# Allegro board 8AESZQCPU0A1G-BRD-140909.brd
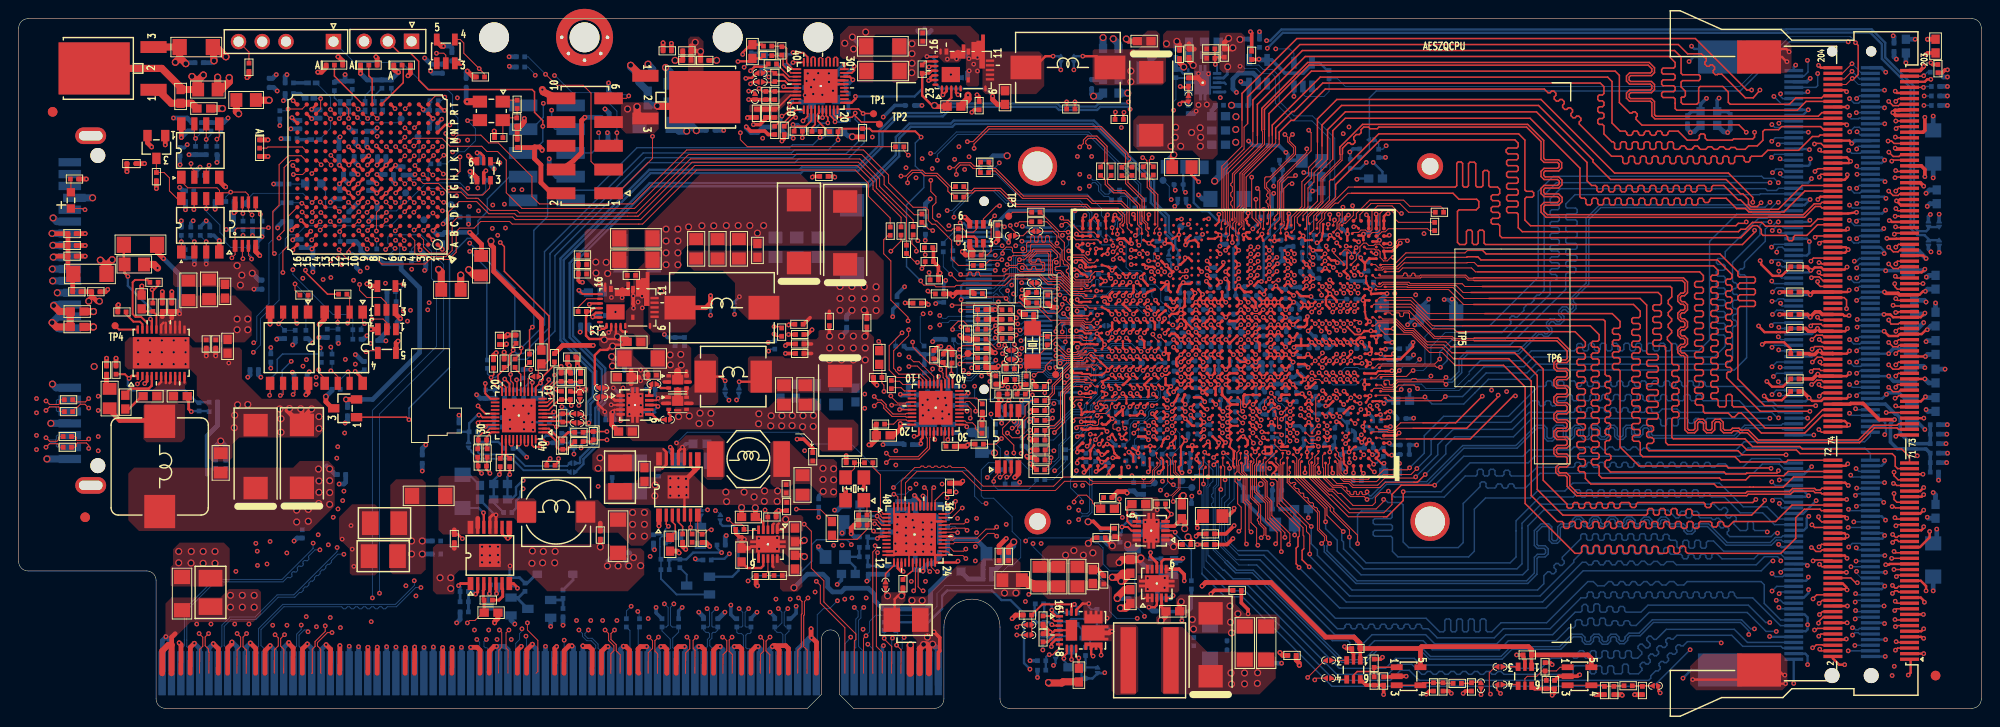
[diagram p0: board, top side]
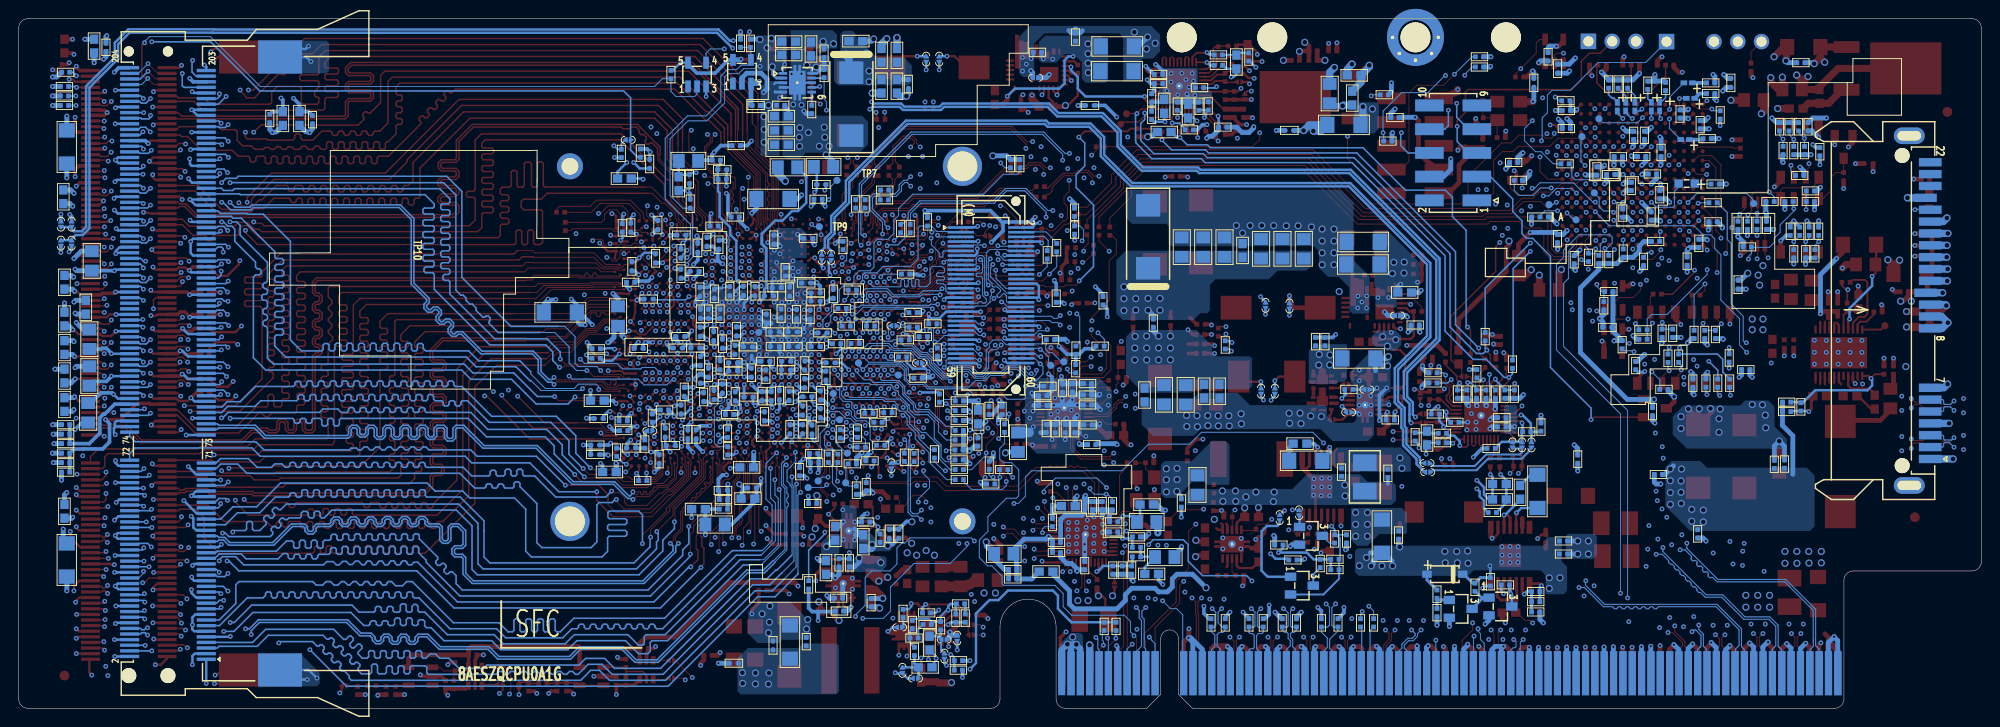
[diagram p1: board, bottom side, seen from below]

Outline 210 x 73.8 mm; copper layers: TOP, L2_GND, L3_SIG, L4_GND, L5_SIG, L6_VCC, L7_VCC, L8_SIG, L9_GND, L10_SIG, L11_GND, BOTTOM. Coordinates in mm from the lower left corner of the outline.
Outline path: 0,72.8 0,15.7 arc(0.29,14.99) 1,14.7 13.7,14.7 arc(14.41,14.41) 14.7,13.7 14.7,1 arc(14.99,0.29) 15.7,0 84.4,0 85.9,1.5 85.9,7.45 arc(86.85,8.4) 87.8,7.45 87.8,1.5 89.3,0 98,0 arc(98.71,0.29) 99,1 99,8.7 arc(102,11.7) 105,8.7 105,1 arc(105.29,0.29) 106,0 209,0 arc(209.71,0.29) 210,1 210,72.8 arc(209.71,73.51) 209,73.8 1,73.8 arc(0.29,73.51) 0,72.8

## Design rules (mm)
net group CLK_LPC1: nets CLK_LPC1 CLK_LPC1_R
net group PCIE0_MB_TX0_N: nets PCIE0_MB_TX0_C_N PCIE0_MB_TX0_N
net group PCIE0_MB_TX0_P: nets PCIE0_MB_TX0_C_P PCIE0_MB_TX0_P
net group PCIE0_MB_TX1_N: nets PCIE0_MB_TX1_C_N PCIE0_MB_TX1_N
net group PCIE0_MB_TX1_P: nets PCIE0_MB_TX1_C_P PCIE0_MB_TX1_P
net group PCIE0_MB_TX2_N: nets PCIE0_MB_TX2_C_N PCIE0_MB_TX2_N
net group PCIE0_MB_TX2_P: nets PCIE0_MB_TX2_C_P PCIE0_MB_TX2_P
net group PCIE0_MB_TX3_N: nets PCIE0_MB_TX3_C_N PCIE0_MB_TX3_N
net group PCIE0_MB_TX3_P: nets PCIE0_MB_TX3_C_P PCIE0_MB_TX3_P
net group PCIE0_MB_TX4_N: nets PCIE0_MB_TX4_C_N PCIE0_MB_TX4_N
net group PCIE0_MB_TX4_P: nets PCIE0_MB_TX4_C_P PCIE0_MB_TX4_P
net group PCIE0_MB_TX5_N: nets PCIE0_MB_TX5_C_N PCIE0_MB_TX5_N
net group PCIE0_MB_TX5_P: nets PCIE0_MB_TX5_C_P PCIE0_MB_TX5_P
net group PCIE0_MB_TX6_N: nets PCIE0_MB_TX6_C_N PCIE0_MB_TX6_N
net group PCIE0_MB_TX6_P: nets PCIE0_MB_TX6_C_P PCIE0_MB_TX6_P
net group PCIE0_MB_TX7_N: nets PCIE0_MB_TX7_C_N PCIE0_MB_TX7_N
net group PCIE0_MB_TX7_P: nets PCIE0_MB_TX7_C_P PCIE0_MB_TX7_P
net group SATA3G_RX0_C_DN: nets SATA3G_RX0_C_DN SATA3G_RX_DN0
net group SATA3G_RX0_C_DP: nets SATA3G_RX0_C_DP SATA3G_RX_DP0
net group SATA6G_RX_DN0: nets SATA6G_RX0_C_DN SATA6G_RX_DN0
net group SATA6G_RX_DP0: nets SATA6G_RX0_C_DP SATA6G_RX_DP0
net group SATA6G_TX_DN0: nets SATA6G_TX0_C_DN SATA6G_TX_DN0
net group SATA6G_TX_DP0: nets SATA6G_TX0_C_DP SATA6G_TX_DP0
net group SGMII_RX_C_DN1: nets SGMII_RX_C_DN1 SGMII_RX_DN1
net group SGMII_RX_C_DP1: nets SGMII_RX_C_DP1 SGMII_RX_DP1
net group SVID_ALERT_N: nets N16898543 SVID_ALERT_N
net group XDP_DFX_PORT_CLK0: nets N16925199 XDP_DFX_PORT_CLK0
net group XDP_DFX_PORT_CLK1: nets N16925202 XDP_DFX_PORT_CLK1
nets with their own width: min track width 0.254; nets GND

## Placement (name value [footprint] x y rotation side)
A1  3.5mm_8via  [A126_DG_3]  60.55 71.8 90 top
B1  Fiducial mark  [2B]  3.63 63.83 0 top
B2  Fiducial mark  [2B]  7.11 20.45 180 top
B3  Fiducial mark  [2B]  205.1 3.51 0 top
C1  0.1U 25V  [C0402]  96.72 71.83 90 top
C2  10uF 6.3V  [C0603]  205.1 70.87 90 top
C3  10UF 25V  [C1206]  92.46 70.84 180 top
C4  47uF 10V  [C1206]  19 70.76 0 top
C5  0.1U 25V  [C0402]  71.5 70.36 180 top
C6  47pF 2% 50V  [C0402]  81.66 70.36 270 top
C7  0.1U 25V  [C0402]  125.22 70.1 90 top
C8  0.1U 25V  [C0402]  124.21 69.98 90 top
C9  0.1U 25V  [C0402]  131.93 69.88 90 top
C10  1000P 50V  [C0402]  127.55 69.56 180 top
C11  0.1U 25V  [C0402]  71.5 69.34 180 top
C12  0.1U 25V  [C0402]  73.41 69.34 0 top
C13  *68pF 50V  [C0402]  24.64 68.61 270 top
C14  CAP 1U 10V  [C0402]  205.36 68.45 270 top
C15  10UF 25V  [C1206]  92.48 68.2 180 top
C16  3.3nF 50V  [C0402]  80.91 67.51 270 top
C17  0.1U 25V  [C0402]  69.39 70.36 0 top
C18  47uF 6.3V  [C0805]  20.24 66.22 0 top
C19  10NF 50V  [C0402]  80.91 65.58 270 top
C20  0.22uF 16V  [C0603]  105.54 65.35 90 top
C21  22uF 6.3V  [C0805]  24.33 65.1 0 top
C22  680U 2.5V  [C7343]  121.18 64.69 270 top
C23  0.1U 25V  [C0402]  102.77 64.49 270 top
C24  1uF 25V  [C0603]  100.08 64.39 0 top
C25  4.7UF 6.3V  [C0402]  79.92 63.68 270 top
C26  0.1uF 16V  [C0402]  80.91 63.68 270 top
C27  0.1uF 16V  [C0402]  51.37 61.07 180 top
C28  0.1uF 16V  [C0402]  53.34 60.45 270 top
C29  0.1uF 16V  [C0402]  103.37 58.45 180 top
C30  1uF 6.3V  [C0402-HANK]  12.06 58.29 180 top
C31  0.1uF 16V  [C0402]  120.33 57.51 90 top
C32  0.1uF 16V  [C0402]  121.4 57.51 90 top
C33  0.1uF 16V  [C0402]  115.77 57.48 90 top
C34  0.1uF 16V  [C0402]  119.12 57.48 90 top
C35  0.1uF 16V  [C0402]  116.89 57.47 90 top
C36  0.1uF 16V  [C0402]  118.04 57.45 90 top
C37  0.1uF 16V  [C0402]  103.34 57.33 180 top
C38  0.1U 25V  [C0402]  86.16 56.92 0 top
C39  0.1uF 16V  [C0402]  14.73 56.9 270 top
C40  0.1uF 16V  [C0402]  100.68 55.83 180 top
C41  0.1uF 16V  [C0402]  100.68 54.71 180 top
C42  0.1uF 16V  [C0402]  5.71 50.8 0 top
C43  680U 2.5V  [C7343]  83.49 51.03 90 top
C44  680U 2.5V  [C7343]  88.43 50.88 90 top
C45  10UF 25V  [C1206]  66.04 50.29 0 top
C46  0.1uF 16V  [C0402]  5.71 49.53 0 top
C47  47uF 6.3V  [C0805]  72.49 49.17 90 top
C48  47uF 6.3V  [C0805]  74.78 49.17 90 top
C49  47uF 6.3V  [C0805]  77.06 49.17 90 top
C50  0.1U 25V  [C0402]  60.33 48.51 180 top
C51  0.1uF 16V  [C0402]  5.71 48.39 0 top
C52  10UF 25V  [C1206]  66.04 48.01 0 top
C53  4.7uF 25V  [C0805]  12.37 47.5 0 top
C54  0.1U 25V  [C0402]  60.33 47.5 180 top
C55  22uF 6.3V  [C0805]  49.48 47.37 270 top
C56  CAP 1U 10V  [C0402]  190.06 47.25 180 top
C57  22uF 16V  [C1206]  7.62 46.48 0 top
C58  0.1U 25V  [C0402]  60.33 46.48 180 top
C59  0.1U 25V  [C0402]  65.56 46.33 0 top
C60  22U 25V  [C0805]  20.37 44.83 90 top
C61  22uF 6.3V  [C0805]  46.25 44.78 0 top
C62  22U 25V  [C0805]  18.16 44.73 90 top
C63  1uF 25V  [C0603]  22.07 44.63 270 top
C64  0.1uF 16V  [C0402]  8.26 44.58 0 top
C65  CAP 1U 10V  [C0402]  190.06 44.55 180 top
C66  1uF 25V  [C0603]  13.16 43.48 270 top
C67  0.1U 25V  [C0402]  96.14 43.36 0 top
C68  0.1U 25V  [C0402]  15.37 42.93 90 top
C69  0.1U 25V  [C0402]  16.38 42.93 90 top
C70  0.1uF 16V  [C0402]  103.05 42.66 0 top
C71  18pF 50V  [C0402]  108.17 42.17 180 top
C72  CAP 1U 10V  [C0402]  190.06 42.15 180 top
C73  0.1U 25V  [C0402]  86.74 41.4 270 top
C74  0.1U 25V  [C0402]  90.75 41.25 270 top
C75  0.1U 25V  [C0402]  83.49 41.1 0 top
C76  *10uF 6.3V  [C0603]  6.26 40.81 0 top
C77  CAP 1U 10V  [C0402]  190.06 40.65 180 top
C78  1uF 6.3V  [C0402]  105.66 40.62 180 top
C79  0.1U 25V  [C0402]  83.57 40.01 0 top
C80  ***22P 50V  [C0402]  53.21 39.5 90 top
C81  0.1U 25V  [C0402]  51.44 39.37 90 top
C82  1uF 25V  [C0603]  65.84 39.22 0 top
C83  0.1U 25V  [C0402]  20.07 38.99 270 top
C84  0.1U 25V  [C0402]  21.08 38.99 270 top
C85  0.1U 25V  [C0402]  83.57 38.99 0 top
C86  1uF 25V  [C0603]  22.35 38.73 90 top
C87  0.1U 25V  [C0402]  83.57 37.97 0 top
C88  CAP 1U 10V  [C0402]  190.06 37.95 180 top
C89  0.1U 25V  [C0402]  59.18 37.59 180 top
C90  10UF 25V  [C1206]  66.6 37.44 180 top
C91  0.1uF 16V  [C0402]  99.87 37.4 90 top
C92  470pF 50V  [C0402]  9.4 36.2 90 top
C93  0.1U 25V  [C0402]  67.79 35.65 180 top
C94  4.7UF 6.3V  [C0402]  58.04 35.43 90 top
C95  0.1uF 16V  [C0402]  59.05 35.43 90 top
C96  1uF 25V  [C0603]  64.8 35.43 180 top
C97  CAP 1U 10V  [C0402]  190.06 35.25 180 top
C98  18pF 50V  [C0402]  107.8 35.11 270 top
C99  CAP 1U 10V  [C0402]  190.04 33.91 180 top
C100  47uF 6.3V  [C0805]  81.89 33.53 270 top
C101  47uF 6.3V  [C0805]  84.18 33.53 270 top
C102  10NF 50V  [C0402]  58.09 33.49 90 top
C103  0.1uF/25V 10%  [C0603]  14.05 33.4 180 top
C104  10NF 50V  [C0402]  5.33 33.02 180 top
C105  680U 2.5V  [C7343]  87.88 32.18 270 top
C106  10NF 50V  [C0402]  5.33 31.75 180 top
C107  3.3nF 50V  [C0402]  58.22 31.08 90 top
C108  1uF 25V  [C0603]  64.92 29.62 180 top
C109  10NF 50V  [C0402]  5.21 29.08 180 top
C110  100P 50V  [C0402]  49.62 28.72 180 top
C111  47pF 2% 50V  [C0402]  58.22 28.16 90 top
C112  10NF 50V  [C0402]  5.21 27.94 180 top
C113  0.1U 25V  [C0402]  84.96 26.92 270 top
C114  CAP 330U 6.3V 20%  [C7343]  30.3 26.97 90 top
C115  CAP 330U 6.3V 20%  [C7343]  25.35 26.95 90 top
C116  8.2PF 50V  [C0402]  88.98 26.28 180 top
C117  47uF 6.3V  [C0805]  21.62 26.26 90 top
C118  1uF 25V  [C0603]  66.95 25.02 270 top
C119  22uF 25V  [C1210]  64.34 24.74 270 top
C120  22uF 6.3V  [C0805]  83.87 23.9 270 top
C121  0.1U 25V  [C0402]  82.12 23.5 270 top
C122  680pF 50V  [C0603]  119.85 21.85 0 top
C123  0.1U 25V  [C0402]  82.17 21.59 90 top
C124  1uF 25V  [C0603]  124.46 21.03 270 top
C125  8.2PF 50V  [C0402]  90.32 20.68 180 top
C126  1uF 25V  [C0603]  78.08 20.47 0 top
C127  10uF 25V  [C1210]  39.14 19.81 180 top
C128  0.1U 25V  [C0402]  117.27 18.82 90 top
C129  0.1U 25V  [C0402]  127.51 18.67 0 top
C130  1uF 25V  [C0603]  83.06 18.56 90 top
C131  0.1U 25V  [C0402]  62.23 18.54 270 top
C132  22uF 16V  [C1206]  64.14 18.41 270 top
C133  0.1U 25V  [C0402]  115.82 18.26 180 top
C134  1200pF 25V  [C0402]  71.04 18.21 270 top
C135  0.1U 25V  [C0402]  46.61 18.16 270 top
C136  1uF 25V  [C0603]  69.7 17.55 90 top
C137  0.1uF 16V  [C0402]  124.97 17.53 0 top
C138  0.1U 25V  [C0402]  127.51 17.53 0 top
C139  680pF 50V  [C0603]  77.35 16.4 90 top
C140  10uF 25V  [C1210]  39.01 16.28 180 top
C141  0.1U 25V  [C0402]  104.9 16.26 90 top
C142  0.1U 25V  [C0402]  105.92 16.26 90 top
C143  10uF 6.3V  [C0603]  83.06 15.64 90 top
C144  10uF 6.3V  [C0603]  118.95 15.19 270 top
C145  10U 16V  [C0805]  109.22 14.1 90 top
C146  10U 16V  [C0805]  111.25 14.1 90 top
C147  10U 16V  [C0805]  113.28 14.1 90 top
C148  1uF 25V  [C0603]  114.94 14.1 270 top
C149  0.1uF 16V  [C0402]  116.1 13.74 90 top
C150  0.1U 25V  [C0402]  130.38 12.62 180 top
C151  10uF 25V  [C1210]  20.52 12.4 90 top
C152  1uF 25V  [C1206]  17.48 12.28 90 top
C153  1uF 25V  [C0603]  118.95 11.96 270 top
C154  1uF 25V  [C0603]  123.49 10.38 180 top
C155  1uF 25V  [C0603]  50.55 10.24 180 top
C156  *0.1uF 16V  [C0402]  107.93 9.98 180 top
C157  10uF 25V  [C1210]  94.95 9.45 180 top
C158  100P 50V  [C0402]  109.61 9.44 270 top
C159  100U 6.3V  [C1206]  131.19 6.99 90 top
C160  100U 6.3V  [C1206]  133.48 6.99 90 top
C161  680U 2.5V  [C7343]  127.53 6.81 90 top
C162  0.1U 25V  [C0402]  143.08 6.4 180 top
C163  0.1U 25V  [C0402]  161.42 5.71 180 top
C164  0.1U 25V  [C0402]  136.25 5.66 180 top
C165  2.2U / 10V  [C0603]  113.44 3.55 270 top
C166  0.1U 25V  [C0402]  146.05 2.92 90 top
C167  0.1U 25V  [C0402]  164.34 2.54 90 top
C168  *CAP 1U 10V  [C0402]  155.45 2.29 270 top
C169  *CAP 1U 10V  [C0402]  173.74 1.91 270 top
C170  0.1U 25V  [C0402]  96.93 71.83 90 bottom
C171  10uF 6.3V  [C0603]  120.42 71.4 180 bottom
C172  10uF 6.3V  [C0603]  127.61 71.34 180 bottom
C173  0.1uF 16V  [C0402]  132.77 71.17 90 bottom
C174  10uF 6.3V  [C0603]  201.93 70.87 90 bottom
C175  10UF 25V  [C1206]  92.45 70.83 180 bottom
C176  CAP 1U 10V  [C0402]  200.66 70.74 90 bottom
C177  4.7uF 6.3V  [C0603]  125.22 70.56 90 bottom
C178  0.1U 25V  [C0402]  100.99 70.21 0 bottom
C179  0.1U 25V  [C0402]  123.83 70.1 90 bottom
C180  10uF 6.3V  [C0603]  127.61 69.92 180 bottom
C181  10uF 6.3V  [C0603]  117.68 69.88 90 bottom
C182  10uF 6.3V  [C0603]  116.03 69.88 90 bottom
C183  0.1U 25V  [C0402]  46.35 69.72 270 bottom
C184  0.22uF 16V  [C0603]  79.71 69.16 270 bottom
C185  0.1U 25V  [C0402]  19.3 69.09 0 bottom
C186  1uF 6.3V  [C0402-HANK]  45.34 68.45 270 bottom
C187  10UF 25V  [C1206]  92.48 68.18 180 bottom
C188  1uF 6.3V  [C0402-HANK]  47.88 66.93 270 bottom
C189  1uF 6.3V  [C0402-HANK]  26.8 66.93 270 bottom
C190  1uF 6.3V  [C0402]  88.04 66.85 180 bottom
C191  1uF 6.3V  [C0402-HANK]  114.81 66.8 270 bottom
C192  10uF 6.3V  [C0603]  117.68 66.57 270 bottom
C193  22uF  6.3V  [C0603]  116.03 66.57 270 bottom
C194  47uF 6.3V  [C0805]  69.72 65.79 90 bottom
C195  0.1uF 16V  [C0402]  88.77 65.33 270 bottom
C196  680U 2.5V  [C7343]  120.9 64.64 270 bottom
C197  1000P 50V  [C0402]  128.47 64.53 180 bottom
C198  1uF 6.3V  [C0402-HANK]  95.38 64.52 180 bottom
C199  10NF 50V  [C0402]  86.04 64.44 90 bottom
C200  10NF 50V  [C0402]  83.7 64.44 90 bottom
C201  0.1uF 16V  [C0402]  125.14 64.08 270 bottom
C202  0.1uF 16V  [C0402]  44.4 63.98 0 bottom
C203  0.1uF 16V  [C0402]  32.24 63.6 270 bottom
C204  10NF 50V  [C0402]  88.77 63.45 90 bottom
C205  10uF 6.3V  [C0603]  128.39 63.37 180 bottom
C206  0.1U 25V  [C0402]  62.74 63.22 0 bottom
C207  CAP 1U 10V  [C0402]  183.13 63.12 270 bottom
C208  10uF 6.3V  [C0603]  181.74 63.12 270 bottom
C209  10uF 6.3V  [C0603]  179.96 63.12 270 bottom
C210  CAP 1U 10V  [C0402]  178.56 62.99 270 bottom
C211  0.1uF 16V  [C0402]  30.08 62.46 270 bottom
C212  47uF 10V  [C1206]  68.2 62.43 0 bottom
C213  0.1uF 16V  [C0402]  18.54 62.23 90 bottom
C214  0.1uF 16V  [C0402]  44.4 62.05 180 bottom
C215  1uF 6.3V  [C0402-HANK]  74.04 61.85 180 bottom
C216  10uF 6.3V  [C0603]  128.39 61.84 180 bottom
C217  0.1uF 16V  [C0402]  37.19 61.32 90 bottom
C218  0.1uF 16V  [C0402]  36.05 61.32 90 bottom
C219  10uF 6.3V  [C0603]  128.39 60.32 180 bottom
C220  0.1U 25V  [C0402]  133.22 60.22 180 bottom
C221  100U 6.3V  [C1206]  204.85 60.07 90 bottom
C222  0.1U 25V  [C0402]  17.27 59.56 270 bottom
C223  0.1uF 16V  [C0402]  34.27 59.49 90 bottom
C224  0.1uF 16V  [C0402]  36.34 59.04 0 bottom
C225  0.1uF 16V  [C0402]  38.84 59.03 180 bottom
C226  1uF 6.3V  [C0402-HANK]  142.48 58.25 270 bottom
C227  *0.1uF 16V  [C0402-HANK]  134.72 57.64 180 bottom
C228  0.1uF 16V  [C0402]  41.13 57.51 270 bottom
C229  0.1uF 16V  [C0402]  35.19 57.18 0 bottom
C230  0.1uF 16V  [C0402]  39.65 57.12 180 bottom
C231  1uF 6.3V  [C0402-HANK]  138.23 56.63 270 bottom
C232  10uF 6.3V  [C0603]  139.38 56.14 270 bottom
C233  1uF 6.3V  [C0402-HANK]  124.12 56.05 180 bottom
C234  0.1uF 16V  [C0402]  37.45 55.85 270 bottom
C235  0.1uF 16V  [C0402]  117.33 55.46 180 bottom
C236  0.1uF 16V  [C0402]  34.4 54.97 270 bottom
C237  10uF 6.3V  [C0603]  205.23 54.74 90 bottom
C238  100U 6.3V  [C1206]  129.29 54.51 0 bottom
C239  0.1U 25V  [C0402]  124.46 54.48 180 bottom
C240  0.1uF 16V  [C0402]  117.37 54.4 180 bottom
C241  *33pF 50V  [C0402-HANK]  138.15 54 90 bottom
C242  0.1uF 16V  [C0402]  120.45 53.98 90 bottom
C243  0.1uF 16V  [C0402]  119.43 53.98 90 bottom
C244  0.1uF 16V  [C0402]  38.37 53 270 bottom
C245  0.1uF 16V  [C0402]  35.33 52.68 270 bottom
C246  0.1U 25V  [C0402]  133.32 52.58 180 bottom
C247  0.1uF 16V  [C0402]  28.7 52.07 180 bottom
C248  1uF 6.3V  [C0402-HANK]  141.6 51.71 90 bottom
C249  0.1uF 16V  [C0402]  22.99 51.69 270 bottom
C250  23.7 ohm NEW  [C0402]  135.59 51.6 0 bottom
C251  1uF 6.3V  [C0402-HANK]  144.5 51.44 90 bottom
C252  0.1U 25V  [C0402]  145.42 51.42 90 bottom
C253  0.1uF 16V  [C0402]  115.64 51.35 90 bottom
C254  0.1uF 16V  [C0402]  114.61 51.34 90 bottom
C255  0.1U 25V  [C0402]  20.45 51.05 270 bottom
C256  10NF 50V  [C0402-HANK]  139.1 50.64 180 bottom
C257  1uF 6.3V  [C0402-HANK]  125.53 50.29 180 bottom
C258  0.1uF 16V  [C0402]  45.35 50.27 270 bottom
C259  680U 2.5V  [C7343]  89.15 50.47 90 bottom
C260  1uF 6.3V  [C0402-HANK]  129.21 50.15 90 bottom
C261  1uF 6.3V  [C0402-HANK]  136.37 49.91 90 bottom
C262  10UF 25V  [C1206]  66.14 49.91 0 bottom
C263  1uF 6.3V  [C0402-HANK]  135.08 49.61 90 bottom
C264  45.3 ohm NEW  [C0402]  121.79 49.53 90 bottom
C265  47uF 6.3V  [C0805]  85.55 49.35 90 bottom
C266  47uF 6.3V  [C0805]  83.26 49.35 90 bottom
C267  47uF 6.3V  [C0805]  80.98 49.35 90 bottom
C268  1uF 6.3V  [C0402-HANK]  137.34 49.28 90 bottom
C269  47uF 6.3V  [C0805]  77.06 49.17 90 bottom
C270  47uF 6.3V  [C0805]  74.78 49.17 90 bottom
C271  47uF 6.3V  [C0805]  72.49 49.17 90 bottom
C272  22uF  6.3V  [C0603]  79.04 49 90 bottom
C273  1uF 6.3V  [C0402-HANK]  139.14 48.68 90 bottom
C274  0.1uF 16V  [C0402]  43.56 48.01 270 bottom
C275  1uF 6.3V  [C0402-HANK]  141.86 48.16 90 bottom
C276  22uF 6.3V  [C0805]  202.18 47.88 90 bottom
C277  0.1uF 16V  [C0402]  31.48 47.85 270 bottom
C278  10UF 25V  [C1206]  66.17 47.5 0 bottom
C279  1uF 6.3V  [C0402-HANK]  144.39 47.3 90 bottom
C280  10NF 50V  [C0402-HANK]  137.67 46.76 0 bottom
C281  1uF 6.3V  [C0402-HANK]  139.14 46.51 270 bottom
C282  10uF 6.3V  [C0603]  205.1 45.59 90 bottom
C283  0.1U 25V  [C0402]  144.53 45.59 0 bottom
C284  1uF 6.3V  [C0402-HANK]  125.74 45.51 180 bottom
C285  1uF 6.3V  [C0402-HANK]  26.04 45.34 90 bottom
C286  1uF 6.3V  [C0402-HANK]  128.89 45.01 0 bottom
C287  1uF 6.3V  [C0402-HANK]  132.46 44.66 90 bottom
C288  1uF 6.3V  [C0402-HANK]  133.91 44.64 90 bottom
C289  1uF 6.3V  [C0402-HANK]  131.22 44.64 90 bottom
C290  1uF 6.3V  [C0402-HANK]  127.51 44.59 90 bottom
C291  1uF 6.3V  [C0402-HANK]  137.11 44.58 270 bottom
C292  0.22uF 16V  [C0603]  61.7 44.5 0 bottom
C293  1uF 6.3V  [C0402-HANK]  124.73 44.45 180 bottom
C294  1uF 6.3V  [C0402-HANK]  135.56 44.36 90 bottom
C295  1uF 6.3V  [C0402-HANK]  122.83 44.35 90 bottom
C296  1uF 6.3V  [C0402-HANK]  129.73 44.13 180 bottom
C297  0.1U 25V  [C0402]  98.98 43.89 270 bottom
C298  0.1U 25V  [C0402]  93.98 43.61 270 bottom
C299  1uF 6.3V  [C0402-HANK]  124.73 43.58 180 bottom
C300  0.1uF 16V  [C0402]  40.39 43.08 270 bottom
C301  10uF 6.3V  [C0603]  202.82 42.93 90 bottom
C302  100U 6.3V  [C1206]  152.04 42.37 0 bottom
C303  1uF 6.3V  [C0402-HANK]  128.42 42.25 270 bottom
C304  1uF 6.3V  [C0402-HANK]  137.06 42.22 270 bottom
C305  1uF 6.3V  [C0402-HANK]  136.2 42.22 270 bottom
C306  1uF 6.3V  [C0402-HANK]  134.95 42.22 270 bottom
C307  1uF 6.3V  [C0402-HANK]  126.77 42.17 90 bottom
C308  1uF 6.3V  [C0402-HANK]  125.31 42.12 90 bottom
C309  47uF 6.3V  [C0805]  145.87 41.97 90 bottom
C310  1uF 6.3V  [C0402-HANK]  130 41.69 90 bottom
C311  10uF 6.3V  [C0603]  205.1 41.66 90 bottom
C312  0.1uF 16V  [C0402]  112.18 41.15 0 bottom
C313  0.1U 25V  [C0402]  88.6 41.22 270 bottom
C314  0.1U 25V  [C0402]  60.58 41.02 0 bottom
C315  1uF 6.3V  [C0402-HANK]  40.01 40.77 0 bottom
C316  1uF 6.3V  [C0402-HANK]  133.2 40.34 90 bottom
C317  1uF 6.3V  [C0402-HANK]  137.08 40.29 90 bottom
C318  1uF 6.3V  [C0402-HANK]  129.09 40.28 0 bottom
C319  1uF 6.3V  [C0402-HANK]  127.19 40.28 0 bottom
C320  1uF 6.3V  [C0402-HANK]  123.99 40.18 180 bottom
C321  1U 10V  [C0402-HANK]  135.64 39.83 270 bottom
C322  1U 10V  [C0402-HANK]  139.21 39.79 180 bottom
C323  0.1uF 16V  [C0402]  113.21 39.78 180 bottom
C324  22uF 6.3V  [C0805]  202.44 39.5 90 bottom
C325  0.1U 25V  [C0402]  71.25 39.24 90 bottom
C326  0.1U 25V  [C0402]  70.23 39.24 90 bottom
C327  *68pF 50V  [C0402]  120.5 39.04 0 bottom
C328  1uF 6.3V  [C0402-HANK]  134.7 39.02 270 bottom
C329  1uF 6.3V  [C0402-HANK]  129.07 38.71 0 bottom
C330  1uF 6.3V  [C0402-HANK]  127.11 38.71 180 bottom
C331  1uF 6.3V  [C0402-HANK]  124.73 38.71 180 bottom
C332  1uF 6.3V  [C0402-HANK]  131.97 38.68 0 bottom
C333  10uF 6.3V  [C0603]  205.1 38.61 90 bottom
C334  1U 10V  [C0402-HANK]  139.47 38.56 180 bottom
C335  1U 10V  [C0402-HANK]  137.59 38.56 0 bottom
C336  1U 10V  [C0402-HANK]  143.66 38.51 0 bottom
C337  1uF 6.3V  [C0402-HANK]  133.35 38.36 90 bottom
C338  0.1U 25V  [C0402]  26.97 37.49 270 bottom
C339  10UF 25V  [C1206]  66.6 37.44 180 bottom
C340  1uF 6.3V  [C0402-HANK]  137.06 37.17 270 bottom
C341  1U 10V  [C0402-HANK]  130.1 37.13 180 bottom
C342  1uF 6.3V  [C0402-HANK]  127.88 37.13 0 bottom
C343  1uF 6.3V  [C0402-HANK]  133.54 36.98 0 bottom
C344  1uF 6.3V  [C0402-HANK]  123.13 36.98 180 bottom
C345  1uF 6.3V  [C0402-HANK]  134.95 36.71 270 bottom
C346  1uF 6.3V  [C0402-HANK]  125.88 36.69 270 bottom
C347  0.1uF 16V  [C0402]  36.98 36.68 90 bottom
C348  0.1U 25V  [C0402]  25.2 36.25 180 bottom
C349  1uF 6.3V  [C0402-HANK]  127.9 36.22 0 bottom
C350  1uF 6.3V  [C0402-HANK]  133.54 36.09 0 bottom
C351  1U 10V  [C0402-HANK]  136.19 35.92 270 bottom
C352  1uF 6.3V  [C0402-HANK]  131.6 35.92 270 bottom
C353  1uF 6.3V  [C0402-HANK]  130.05 35.72 90 bottom
C354  1uF 6.3V  [C0402-HANK]  123.62 35.59 270 bottom
C355  10uF 6.3V  [C0603]  205.1 35.56 90 bottom
C356  22uF 6.3V  [C0805]  202.44 35.56 90 bottom
C357  1uF 6.3V  [C0402-HANK]  137.07 35.27 90 bottom
C358  0.1uF 16V  [C0402]  30.86 34.8 90 bottom
C359  1uF 6.3V  [C0402-HANK]  125.91 34.78 90 bottom
C360  CAP 1U 10V  [C0402]  99.87 34.47 0 bottom
C361  CAP 1U 10V  [C0402]  97.26 34.29 270 bottom
C362  0.1uF 16V  [C0402]  98.32 34.26 270 bottom
C363  1uF 6.3V  [C0402-HANK]  134.7 34.21 270 bottom
C364  0.1U 25V  [C0402]  67.67 34.14 0 bottom
C365  22uF  6.3V  [C0603]  81.51 33.93 270 bottom
C366  1uF 6.3V  [C0402-HANK]  138.79 33.86 90 bottom
C367  10NF 50V  [C0402]  55.04 33.62 270 bottom
C368  10NF 50V  [C0402]  53.01 33.62 270 bottom
C369  10NF 50V  [C0402]  49.96 33.62 270 bottom
C370  47uF 6.3V  [C0805]  87.45 33.55 270 bottom
C371  47uF 6.3V  [C0805]  85.13 33.54 270 bottom
C372  0.1uF 16V  [C0402]  95.63 33.54 0 bottom
C373  1uF 6.3V  [C0402-HANK]  135.61 33.53 270 bottom
C374  22uF  6.3V  [C0603]  89.53 33.53 270 bottom
C375  1uF 6.3V  [C0402-HANK]  128.6 33.51 270 bottom
C376  1uF 6.3V  [C0402-HANK]  124.2 33.49 90 bottom
C377  1uF 6.3V  [C0402-HANK]  127.56 33.44 270 bottom
C378  1uF 6.3V  [C0402-HANK]  130.46 33.41 270 bottom
C379  1uF 6.3V  [C0402-HANK]  129.47 33.41 270 bottom
C380  1uF 6.3V  [C0402-HANK]  133.33 33.38 270 bottom
C381  1uF 6.3V  [C0402-HANK]  125.62 33.35 0 bottom
C382  1uF 6.3V  [C0402-HANK]  136.71 33.31 90 bottom
C383  1uF 6.3V  [C0402-HANK]  131.9 33.31 180 bottom
C384  1uF 6.3V  [C0402]  111.48 33.2 90 bottom
C385  10uF 6.3V  [C0603]  148.08 32.92 180 bottom
C386  10uF 6.3V  [C0603]  205.1 32.51 270 bottom
C387  0.1uF 16V  [C0402]  95.63 32.47 0 bottom
C388  0.1uF 16V  [C0402]  100.41 32.42 180 bottom
C389  1000P 50V  [C0402]  19.3 32.26 270 bottom
C390  *33pF 50V  [C0402-HANK]  139.13 31.98 90 bottom
C391  0.1U 25V  [C0402]  140.89 31.93 0 bottom
C392  0.1uF 16V  [C0402]  104.78 31.88 270 bottom
C393  1uF 6.3V  [C0402-HANK]  126.11 31.86 90 bottom
C394  0.1uF 16V  [C0402]  35.18 31.75 270 bottom
C395  47nF 10V  [C0402]  20.83 31.75 0 bottom
C396  22uF 6.3V  [C0805]  202.56 31.62 270 bottom
C397  1uF 6.3V  [C0402-HANK]  124.21 31.58 270 bottom
C398  0.1U 25V  [C0402]  133.93 31.45 180 bottom
C399  22uF  6.3V  [C0603]  107.35 31.18 270 bottom
C400  0.1uF 16V  [C0402]  51.31 31.11 0 bottom
C401  1uF 6.3V  [C0402-HANK]  147.94 31.01 180 bottom
C402  0.1U 25V  [C0402]  145.31 30.76 180 bottom
C403  0.1uF 16V  [C0402]  204.98 30.35 0 bottom
C404  0.1uF 16V  [C0402]  95.58 30.33 0 bottom
C405  1uF 6.3V  [C0402]  51.31 30.12 0 bottom
C406  0.1uF 16V  [C0402]  100.06 29.95 90 bottom
C407  0.1uF 16V  [C0402]  99.09 29.93 90 bottom
C408  0.1uF 16V  [C0402]  98.02 29.93 90 bottom
C409  0.1uF 16V  [C0402]  97 29.92 90 bottom
C410  1uF 6.3V  [C0402-HANK]  127.48 29.85 270 bottom
C411  1uF 6.3V  [C0402-HANK]  126.11 29.85 270 bottom
C412  1uF 6.3V  [C0402-HANK]  125.12 29.83 270 bottom
C413  0.1U 25V  [C0402]  145.26 29.72 0 bottom
C414  3.3nF 50V  [C0402]  48.64 29.59 180 bottom
C415  1uF 6.3V  [C0402-HANK]  140.82 29.49 270 bottom
C416  0.1U 25V  [C0402]  134.15 29.44 270 bottom
C417  1uF 6.3V  [C0402-HANK]  138.41 29.32 270 bottom
C418  1uF 6.3V  [C0402-HANK]  137.52 29.32 270 bottom
C419  0.22uF 16V  [C0603]  59.31 28.92 270 bottom
C420  10U 16V  [C0805]  103.07 28.47 270 bottom
C421  0.1uF/25V 10%  [C0603]  72.9 28.32 180 bottom
C422  10NF 50V  [C0402-HANK]  148.31 28.18 180 bottom
C423  1uF 6.3V  [C0402-HANK]  140.22 28.12 0 bottom
C424  10NF 50V  [C0402-HANK]  144.47 27.86 0 bottom
C425  23.7 ohm NEW  [C0402]  134.14 27.56 270 bottom
C426  0.1U 25V  [C0402]  124.94 27.28 180 bottom
C427  1uF 6.3V  [C0402-HANK]  148.31 27.16 180 bottom
C428  10NF 50V  [C0402]  115.24 26.87 90 bottom
C429  10NF 50V  [C0402]  114.19 26.84 90 bottom
C430  10NF 50V  [C0402]  123.37 26.75 90 bottom
C431  10NF 50V  [C0402]  122.35 26.75 90 bottom
C432  1uF 6.3V  [C0402-HANK]  141.48 26.67 270 bottom
C433  0.1U 25V  [C0402]  43.18 26.67 270 bottom
C434  0.1uF 16V  [C0402]  204.98 26.29 0 bottom
C435  0.1U 25V  [C0402]  124.84 26.29 180 bottom
C436  0.1U 25V  [C0402]  21.06 26.14 90 bottom
C437  0.1U 25V  [C0402]  22.15 26.11 90 bottom
C438  0.1U 25V  [C0402]  126.44 25.32 90 bottom
C439  22uF  6.3V  [C0603]  146.79 25.29 180 bottom
C440  0.1U 25V  [C0402]  68.45 25.27 270 bottom
C441  0.1U 25V  [C0402]  63.5 25.15 270 bottom
C442  *0.1uF 16V  [C0402]  34.54 25.02 0 bottom
C443  22uF 25V  [C1210]  65.96 24.77 270 bottom
C444  0.22uF 16V  [C0603]  51.56 24 0 bottom
C445  22uF 6.3V  [C0805]  83.87 23.9 270 bottom
C446  1uF 6.3V  [C0402-HANK]  131.53 23.59 0 bottom
C449  *0.1uF 16V  [C0402-HANK]  134.65 23.32 0 bottom
C450  0.1uF/25V 10%  [C0603]  49.35 23.11 270 bottom
C451  10uF 6.3V  [C0603]  131.97 22.44 0 bottom
C452  0.1U 25V  [C0402]  85.6 21.97 90 bottom
C453  0.1U 25V  [C0402]  125.04 21.92 180 bottom
C454  0.1uF 16V  [C0402]  95.11 21.68 270 bottom
C455  CAP 1U 10V  [C0402]  94.06 21.68 270 bottom
C456  1uF 25V  [C0603]  97.69 21.64 180 bottom
C457  22uF  6.3V  [C0603]  137.26 21.32 0 bottom
C458  10uF 6.3V  [C0603]  205.1 21.08 270 bottom
C459  0.1uF 16V  [C0402]  92.84 19.96 0 bottom
C460  10U 16V  [C0805]  89.31 19.94 180 bottom
C461  0.1uF 16V  [C0402]  92.84 18.87 0 bottom
C462  1uF 25V  [C0603]  122.63 18.72 270 bottom
C463  1uF 6.3V  [C0402-HANK]  116.84 18.67 90 bottom
C464  1uF 6.3V  [C0402-HANK]  115.82 18.67 90 bottom
C465  0.1uF 16V  [C0402]  30.35 18.67 270 bottom
C466  0.1U 25V  [C0402]  62.36 18.54 270 bottom
C467  22uF 16V  [C1206]  64.14 18.41 270 bottom
C468  CAP 1U 10V  [C0402]  90.4 18.35 180 bottom
C469  0.1U 25V  [C0402]  44.7 17.91 0 bottom
C470  10uF 6.3V  [C0603]  119.63 17.83 90 bottom
C471  10U 16V  [C0805]  104.6 16.54 0 bottom
C472  0.1U 25V  [C0402]  44.7 16.51 0 bottom
C473  10U 16V  [C0805]  87.37 16.19 180 bottom
C474  100U 6.3V  [C1206]  204.85 15.88 270 bottom
C475  0.1uF 16V  [C0402]  95.93 15.27 90 bottom
C476  680pF 50V  [C0603]  123.62 15.06 270 bottom
C477  0.1uF 16V  [C0402]  103.63 14.86 0 bottom
C478  330pF 50V  [C0402]  69.16 14.83 0 bottom
C479  CAP 1U 10V  [C0402]  92.94 14.79 270 bottom
C480  0.1uF 16V  [C0402]  91.92 14.79 270 bottom
C481  0.1uF 16V  [C0402]  90.9 14.79 270 bottom
C482  CAP 1U 10V  [C0402]  103.63 13.84 0 bottom
C483  4700P 50V  [C0402]  50.93 13.21 0 bottom
C484  33pF 50V  [C0402]  47.68 11.4 180 bottom
C485  0.1uF 16V  [C0402]  118.8 11.3 90 bottom
C486  0.1U 25V  [C0402]  115.37 10.15 270 bottom
C487  68pF 50V  [C0402]  109.73 9.65 90 bottom
C488  3.3nF 50V  [C0402]  108.71 9.65 90 bottom
C489  0.1uF 16V  [C0402]  82.42 9.14 270 bottom
C490  0.1uF 16V  [C0402]  80.9 9.14 270 bottom
C491  0.1uF 16V  [C0402]  78.36 9.14 270 bottom
C492  0.1uF 16V  [C0402]  76.83 9.14 270 bottom
C493  0.1uF 16V  [C0402]  74.8 9.14 270 bottom
C494  0.1uF 16V  [C0402]  73.28 9.14 270 bottom
C495  0.1uF 16V  [C0402]  70.61 9.14 270 bottom
C496  0.1uF 16V  [C0402]  68.83 9.14 270 bottom
C497  2.2nF 50V  [C0402]  114.2 7.52 180 bottom
C498  0.1uF 16V  [C0402]  125.73 7.14 90 bottom
C499  100U 6.3V  [C1206]  127.48 7.09 90 bottom
C500  1uF 6.3V  [C0402-HANK]  129.29 6.73 90 bottom
C501  1uF 6.3V  [C0402-HANK]  133.48 4.83 0 bottom
D1  GREEN KP-1608SGC  [KP_1608]  5.59 54.36 90 top
D2  LTST-C281KGKT  [LED_KPHHS_1005QB]  31.37 66.93 0 bottom
D3  LTST-C281KGKT  [LED_KPHHS_1005QB]  31.11 65.28 0 bottom
D4  LTST-C281KGKT  [LED_KPHHS_1005QB]  38.95 64.39 270 bottom
D5  LTST-C281KGKT  [LED_KPHHS_1005QB]  38.06 64.39 270 bottom
D6  LTST-C281KGKT  [LED_KPHHS_1005QB]  37.07 64.39 270 bottom
D7  LTST-C281KGKT  [LED_KPHHS_1005QB]  35.31 64.39 270 bottom
D8  LTST-C281KGKT  [LED_KPHHS_1005QB]  34.42 64.39 270 bottom
D9  LTST-C281KGKT  [LED_KPHHS_1005QB]  31.7 60.86 0 bottom
D10  GREEN KP-1608SGC  [KP_1608]  31.52 56.16 0 bottom
D11  BZT52C5V1-7-F  [SOD_123]  57.4 14.35 180 bottom
J1  1K 1% 1/16W  [JP3_0402]  33.78 68.83 0 top
J2  1K 1% 1/16W  [JP3_0402]  37.47 68.83 0 top
J3  1K 1% 1/16W  [JP3_0402]  41.02 68.83 0 top
J4  1K 5% 1/16W  [JP3_0402]  25.78 59.94 270 top
J5  1K 5% 1/16W  [JP3_0402]  47.22 52.58 0 bottom
JP1  HEADER PIN (S)  [JP3]  42.04 71.37 180 top
JP2  *HEADER PIN 1*3-1  [JP5A]  33.68 71.35 180 top
JP3  JTAG_2x5_SMD  [JP2X5_SMD_JNPR_1]  60.58 60.2 90 top
JP4  3.5mm_8via  [HEATSINK_60X72_4P]  130.02 37 0 top
JP5  JTAG_2x5_SMD  [JP2X5_SMD_JNPR_1]  56.52 59.44 90 bottom
L1  170nH 61A  [L2_IUT107]  112.27 68.58 0 top
L2  600OHM 25% 300mA  [L0402]  53.29 62.74 90 top
L3  600OHM +/-25% 2A  [L0805]  124.46 57.91 0 top
L4  30OHM 25% 2A  [L0402]  6.22 44.58 180 top
L5  220nH 50A  [L2_IUT107]  75.24 42.87 0 top
L6  *40ohm/100MHZ 0.4A  [L0603]  6.26 42.46 180 top
L7  1.2uH 15A  [L2_INTFV0705]  76.45 35.5 0 top
L8  600ohm/100MHz 25%  [L0603]  92.51 29.22 0 top
L9  2.2uH 20% 3.1A  [L2_DO1813HC]  78.08 26.67 0 top
L10  2.2UH +-20% 16A  [L2_MHCC10040]  15.09 25.88 270 top
L11  4.7UH 20% 3.4A  [L2_SCDS73T]  57.51 21.01 0 top
L12  600OHM +/-25% 2A  [L0805]  127.76 20.57 180 top
L13  600OHM +/-25% 2A  [L0805]  106.3 13.72 180 top
L14  0.55UH 30.2A  [L2_XAL7070]  121.01 5.13 0 top
L15  600OHM +/-25% 2A  [L0805]  138.34 58.58 0 bottom
L16  600OHM +/-25% 2A  [L0805]  123.88 57.94 180 bottom
L17  600OHM +/-25% 2A  [L0805]  127.74 57.89 180 bottom
L18  600ohm/100MHz 25%  [L0603]  89.28 21.8 0 bottom
L19  600OHM +/-25% 2A  [L0805]  135.48 19.67 180 bottom
L20  600ohm/100MHz 25%  [L0603]  100.08 14.63 0 bottom
L21  600ohm/100MHz 25%  [L0603]  88.77 14.38 0 bottom
N1  0ohm  [0_OHM_2PIN]  79.32 67.97 0 top
N2  0ohm  [0_OHM_2PIN]  79.35 67.03 0 top
N3  0ohm  [0_OHM_2PIN]  78.79 65.46 270 top
N4  0ohm  [0_OHM_2PIN]  125.17 65.22 90 top
N5  0ohm  [0_OHM_2PIN]  108.84 51.05 180 top
N6  *0ohm  [0_OHM_2PIN]  106.32 50.57 180 top
N7  0ohm  [0_OHM_2PIN]  108.69 45.54 180 top
N8  0ohm  [0_OHM_2PIN]  106.19 38.31 0 top
N9  0ohm  [0_OHM_2PIN]  106.22 37.34 0 top
N10  0ohm  [0_OHM_2PIN]  55.35 35.5 180 top
N11  0ohm  [0_OHM_2PIN]  67.97 34.7 0 top
N12  0ohm  [0_OHM_2PIN]  62.36 34.29 0 top
N13  0ohm  [0_OHM_2PIN]  60.05 33.39 90 top
N14  *0ohm  [0_OHM_2PIN]  62.28 33.32 0 top
N15  0ohm  [0_OHM_2PIN]  59.72 31.51 180 top
N16  0ohm  [0_OHM_2PIN]  69.42 30.89 0 top
N17  0ohm  [0_OHM_2PIN]  59.74 30.55 180 top
N18  *0ohm  [0_OHM_2PIN]  92.75 13.19 270 top
N19  0ohm  [0_OHM_2PIN]  108.09 8.94 0 top
N20  *0ohm  [0_OHM_2PIN]  108.09 7.85 0 top
N21  0ohm  [0_OHM_2PIN]  140.16 5.13 0 top
N22  0ohm  [0_OHM_2PIN]  158.5 4.45 0 top
N23  0ohm  [0_OHM_2PIN]  140.16 3.23 0 top
N24  0ohm  [0_OHM_2PIN]  158.5 2.54 0 top
N25  0ohm  [0_OHM_2PIN]  156.46 2.41 270 top
N26  0ohm  [0_OHM_2PIN]  175.13 2.41 0 top
N27  0ohm  [0_OHM_2PIN]  112.9 69.47 270 bottom
N28  0ohm  [0_OHM_2PIN]  111.51 69.47 270 bottom
N29  0ohm  [0_OHM_2PIN]  101.19 67.49 0 bottom
N30  0ohm  [0_OHM_2PIN]  144.78 60.83 180 bottom
N31  0ohm  [0_OHM_2PIN]  205.49 51.82 270 bottom
N32  0ohm  [0_OHM_2PIN]  204.34 51.82 270 bottom
N33  0ohm  [0_OHM_2PIN]  205.49 49.78 90 bottom
N34  0ohm  [0_OHM_2PIN]  204.34 49.78 90 bottom
N35  0ohm  [0_OHM_2PIN]  124.08 48.26 90 bottom
N36  0ohm  [0_OHM_2PIN]  123.06 48.26 90 bottom
N37  0ohm  [0_OHM_2PIN]  76.59 43.13 270 bottom
N38  0ohm  [0_OHM_2PIN]  74.03 43.06 270 bottom
N39  0ohm  [0_OHM_2PIN]  62.46 42.04 180 bottom
N40  0ohm  [0_OHM_2PIN]  116.36 40.94 180 bottom
N41  0ohm  [0_OHM_2PIN]  113.61 36.96 180 bottom
N42  0ohm  [0_OHM_2PIN]  65.74 34.11 0 bottom
N43  0ohm  [0_OHM_2PIN]  77.06 33.95 270 bottom
N44  0ohm  [0_OHM_2PIN]  75.59 33.95 270 bottom
N45  0ohm  [0_OHM_2PIN]  67.69 31.67 180 bottom
N46  0ohm  [0_OHM_2PIN]  142.47 29.7 0 bottom
N47  0ohm  [0_OHM_2PIN]  50.16 28.19 90 bottom
N48  0ohm  [0_OHM_2PIN]  49.15 28.19 90 bottom
N49  0ohm  [0_OHM_2PIN]  48.13 28.19 90 bottom
N50  0ohm  [0_OHM_2PIN]  59.31 26.24 180 bottom
N51  0ohm  [0_OHM_2PIN]  116.62 25.96 90 bottom
N52  0ohm  [0_OHM_2PIN]  59.23 25.27 180 bottom
N53  0ohm  [0_OHM_2PIN]  73 20.92 270 bottom
N54  0ohm  [0_OHM_2PIN]  75.08 20.41 270 bottom
N55  0ohm  [0_OHM_2PIN]  115.74 8.66 180 bottom
N56  0ohm  [0_OHM_2PIN]  109.58 7.51 90 bottom
N57  *0ohm  [0_OHM_2PIN]  110.98 7.36 0 bottom
N58  0ohm  [0_OHM_2PIN]  110.95 5.59 270 bottom
N59  0ohm  [0_OHM_2PIN]  115.44 4.06 270 bottom
N60  *0ohm  [0_OHM_2PIN]  114.05 3.2 180 bottom
NOREF  -  []  181.1 136.18 0 top
NOREF#2  ***  []  0.13 16.26 0 top
NOREF#3  -  []  0 0 0 top
NOREF#4  -  []  149.35 2.92 0 top
NOREF#5  -  []  74.42 7.24 180 bottom
NOREF#6  -  []  70.61 7.24 180 bottom
NOREF#7  -  []  94.87 12.19 180 bottom
NOREF#8  ***  [unnamed#2]  50.87 71.8 180 bottom
NOREF#9  -  []  72.77 10.29 180 bottom
NOREF#10  -  []  59.05 8 180 bottom
NOREF#11  -  []  101.73 15.14 270 bottom
NOREF#12  -  []  48.13 6.99 180 bottom
NOREF#13  -  []  99.19 58.29 315 bottom
NOREF#14  -  []  101.85 21.08 315 bottom
NOREF#15  -  []  101.85 18.16 270 bottom
NOREF#16  -  []  119.38 58.55 180 bottom
NOREF#17  -  []  3.3 30.99 270 bottom
NOREF#18  -  []  18.41 7.62 180 bottom
NOREF#19  -  []  35.69 16.13 315 bottom
NOREF#20  -  []  43.94 12.57 315 bottom
NOREF#21  -  []  103.12 59.56 315 bottom
NOREF#22  -  []  91.92 31.47 270 bottom
NOREF#23  -  []  50.55 8 180 bottom
NOREF#24  -  []  114.94 54.99 270 bottom
NOREF#25  -  []  96.01 23.24 180 bottom
NOREF#26  -  []  30.61 18.03 135 bottom
NOREF#27  -  []  105.03 17.53 270 bottom
NOREF#28  -  []  26.54 7.49 180 bottom
NOREF#29  -  []  95.63 35.69 270 bottom
NOREF#30  -  []  100.97 52.2 315 bottom
NOREF#31  -  []  29.34 9.27 135 bottom
NOREF#32  -  []  76.2 10.29 180 bottom
NOREF#33  ***  [unnamed#2]  85.55 71.8 180 bottom
NOREF#34  -  []  66.55 7.24 180 bottom
NOREF#35  -  []  101.22 56.77 315 bottom
NOREF#36  -  []  98.17 42.93 90 bottom
NOREF#37  -  []  88.52 10.41 180 bottom
NOREF#38  -  []  112.65 59.69 180 bottom
NOREF#39  ***  [unnamed#2]  75.87 71.8 180 bottom
NOREF#40  -  []  7.87 26.92 270 bottom
NOREF#41  -  []  78.49 7.24 180 bottom
NOREF#42  -  []  7.87 31.24 270 bottom
NOREF#43  -  []  113.79 19.3 270 bottom
NOREF#44  -  []  93.22 25.4 270 bottom
NOREF#45  -  []  34.42 7.75 315 bottom
NOREF#46  -  []  85.34 12.19 0 bottom
NOREF#47  -  []  61.85 8 180 bottom
NOREF#48  -  []  80.39 10.29 180 bottom
NOREF#49  -  []  3.3 27.05 270 bottom
NOREF#50  -  []  22.48 7.62 180 bottom
NOREF#51  -  []  115.32 19.68 180 bottom
NOREF#52  -  []  96.01 55.88 315 bottom
NOREF#53  -  []  68.2 10.79 180 bottom
NOREF#54  -  []  158.37 6.48 180 bottom
NOREF#55  -  []  64.14 7.11 180 bottom
P1  SODIMM-204P  [SODIMM_204R]  198.22 3.5 90 top
P2  *CONN60_ITP-XDP  [BSH_60_01_A]  105.96 44.2 270 bottom
P3  SATA CONN  [SATA2_R_SMD]  8.47 59.16 270 bottom
P4  SODIMM-204P_R  [SODIMM_204R_R]  194.03 3.5 90 bottom
Q1  RT9164APL  [TO_252AA]  9.86 68.48 90 top
Q2  RT9164APL  [TO_252AA]  71.63 65.41 270 top
R1  49.9 1% 1/10W  [R0603]  120.42 71.4 180 top
R2  5.9K 1% 1/16W  [R0402]  80.14 70.87 0 top
R3  10K 1% 1/16W  [R0402]  127.55 70.58 180 top
R4  6.49K 1% 1/10W  [R0603]  78.51 70.28 270 top
R5  10K 1% 1/16W  [R0402]  129 70.12 270 top
R6  5.9K 1% 1/16W  [R0402]  80.14 69.85 0 top
R7  4.75K 0.1% 1/16W  [R0402]  80.64 68.96 0 top
R8  4.75K 1% 1/16W  [R0402]  96.67 68.4 90 top
R9  1K 1% 1/16W  [R0402]  49.4 67.56 0 top
R10  1K 1% 1/16W  [R0402]  125.17 67.02 90 top
R11  13K 1% 1/16W  [R0402]  79.94 65.58 90 top
R12  240 5% 1/10W  [R0603]  17.32 65.48 270 top
R13  10K 1% 1/16W  [R0402]  53.33 64.63 90 top
R14  100 1% 1/10W  [R0603]  19.81 64.19 180 top
R15  10K 1% THERMISTOR NEW  [R0402]  112.57 64.14 180 top
R16  75 1% 1/16W  [R0402]  78.93 63.68 90 top
R17  47K 1% THERMISTOR NEW  [R0402]  117.75 63.02 180 top
R18  4.75K 0.1% 1/16W  [R0402]  80.9 61.85 90 top
R19  13K 1% 1/16W  [R0402]  81.92 61.85 90 top
R20  0ohm 5% 1/16W  [R0402]  83.42 61.76 180 top
R21  150 1% 1/16W  [R0402]  85.32 61.73 180 top
R22  10 1% 1/16W  [R0402]  87.23 61.71 180 top
R23  100ohm 1% 1/16W  [R0402]  90.3 61.59 90 top
R24  33.2 1% 1/16W  [R0402]  94.26 60.09 0 top
R25  220 1% 1/16W  [R0402]  5.97 56.64 180 top
R26  22.1 1% 1/16W  [R0402]  108.84 53.09 0 top
R27  100ohm 1% 1/16W  [R0402]  152.02 53.09 180 top
R28  22.1 1% 1/16W  [R0402]  96.65 52.45 270 top
R29  220 5% 1/16W  [R0402]  108.84 52.07 180 top
R30  100ohm 1% 1/16W  [R0402]  151.51 51.56 270 top
R31  10K 1% 1/16W  [R0402]  104.77 51.28 90 top
R32  33.2 1% 1/16W  [R0402]  95.71 51.1 270 top
R33  33.2 1% 1/16W  [R0402]  94.41 51.08 270 top
R34  15ohm 1% 1/16W  [R0402]  93.25 51.06 90 top
R35  1K 1% 1/16W  [R0402]  100.53 50.88 270 top
R36  0ohm 5% 1/4W  [R1206]  13.03 49.61 180 top
R37  10K 1% 1/16W  [R0402]  97.36 49.3 0 top
R38  33.2 1% 1/16W  [R0402]  95 49.12 270 top
R39  49.9 1% 1/10W  [R0603]  79.04 49 90 top
R40  10K 1% 1/16W  [R0402]  102.54 48.51 0 top
R41  1K 1% 1/16W  [R0402]  97.43 47.8 180 top
R42  33.2 1% 1/16W  [R0402]  102.59 47.4 0 top
R43  1K 1% 1/16W  [R0402]  97.97 45.85 180 top
R44  100K 1% 1/16W  [R0402]  14.48 45.59 180 top
R45  100ohm 1% 1/16W  [R0402]  108.46 44.5 180 top
R46  10K 1% 1/16W  [R0402]  102.67 44.37 0 top
R47  1K 1% 1/16W  [R0402]  98.53 44.35 180 top
R48  15ohm 1% 1/16W  [R0402]  34.67 44.32 180 top
R49  15 1% 1/16W  [R0402]  30.53 44.22 0 top
R50  49.9 1% 1/16W  [R0402]  110.11 43.79 270 top
R51  51 5% 1/16W  [R0402]  108.48 43.38 0 top
R52  100K 1% 1/16W  [R0402]  14.35 42.93 270 top
R53  1K 1% 1/16W  [R0402]  105.66 42.65 0 top
R54  4.75K 1% 1/16W  [R0402]  60.3 42.47 180 top
R55  86.6K 1% 1/16W  [R0402]  11.05 42.42 0 top
R56  *1K 1% 1/16W  [R0402]  105.66 41.63 180 top
R57  4.75K 1% 1/16W  [R0402]  103.07 41.63 180 top
R58  1K 1% 1/16W  [R0402]  103.05 40.58 180 top
R59  10K 1% THERMISTOR NEW  [R0402]  81.64 40.26 90 top
R60  *1K 1% 1/16W  [R0402]  101.54 40.05 270 top
R61  1K 1% 1/16W  [R0402]  105.66 39.6 0 top
R62  2.21K 1/16W  [R0402]  103.05 39.5 0 top
R63  10M 5% 1/16W  [R0402]  110.06 39.35 90 top
R64  51 5% 1/16W  [R0402]  103.05 38.51 0 top
R65  2.21K 1/16W  [R0402]  97.92 37.85 270 top
R66  56.2 1% 1/10W  [R0603]  55.93 37.59 90 top
R67  15 1% 1/10W  [R0603]  92.08 37.54 270 top
R68  13K 1% 1/16W  [R0402]  57.33 37.52 270 top
R69  51 5% 1/16W  [R0402]  103.05 37.49 0 top
R70  150 1% 1/16W  [R0402]  54.66 37.47 270 top
R71  *2.21K 1/16W  [R0402]  98.93 37.47 90 top
R72  4.75K 1% 1/16W  [R0402]  51.94 36.93 270 top
R73  10 1% 1/16W  [R0402]  53.11 36.93 270 top
R74  4.75K 1% 1/16W  [R0402]  50.8 36.86 270 top
R75  51 5% 1/16W  [R0402]  103.05 36.47 0 top
R76  51 5% 1/16W  [R0402]  106.09 36.33 180 top
R77  10K 1% 1/16W  [R0402]  10.41 36.2 270 top
R78  4.75K 1% 1/16W  [R0402]  91.92 35.41 180 top
R79  75 1% 1/16W  [R0402]  60.12 35.4 270 top
R80  1K 1% 1/16W  [R0402]  106.15 35.2 0 top
R81  10K 1% 1/16W  [R0402]  104.55 35.13 90 top
R82  *475 1% 1/16W  [R0402]  93.37 34.65 90 top
R83  10K 1% 1/16W  [R0402]  109.3 34.44 0 top
R84  10K 1% 1/16W  [R0402]  105.33 33.63 0 top
R85  *1K 1% 1/16W  [R0402]  107.26 33.63 0 top
R86  13K 1% 1/16W  [R0402]  59.03 33.49 270 top
R87  10K 5% 1/10W  [R0603]  17.3 33.4 180 top
R88  2.7 1% 1/8W  [R0805]  9.73 33.15 90 top
R89  15ohm 1% 1/16W  [R0402]  109.35 32.93 180 top
R90  2.7 5% 1/10W  [R0603]  11.4 32.77 270 top
R91  *2.21K 1/16W  [R0402]  103.11 32.14 90 top
R92  10K 1% 1/16W  [R0402]  109.35 31.86 0 top
R93  15ohm 1% 1/16W  [R0402]  109.37 30.82 180 top
R94  *2.21K 1/16W  [R0402]  92.21 30.41 0 top
R95  *2.21K 1/16W  [R0402]  103.08 29.88 270 top
R96  15ohm 1% 1/16W  [R0402]  109.36 29.74 180 top
R97  5.9K 1% 1/16W  [R0402]  59.94 29.54 180 top
R98  6.49K 1% 1/16W  [R0402]  61.48 29.17 90 top
R99  1K 1% 1/16W  [R0402]  109.36 28.71 180 top
R100  5.9K 1% 1/16W  [R0402]  59.94 28.54 180 top
R101  10K 1% 1/16W  [R0402]  102.78 28.27 0 top
R102  *2.21K 1/16W  [R0402]  99.66 28.04 180 top
R103  *4.75K 1% 1/16W  [R0402]  109.39 27.65 180 top
R104  3.16K 1/16W  [R0402]  49.11 27.32 90 top
R105  3.16K 1/16W  [R0402]  50.13 27.32 90 top
R106  1K 1% 1/16W  [R0402]  109.38 26.58 180 top
R107  301  1%  1/16W  [R0402]  51.53 26.3 270 top
R108  301  1%  1/16W  [R0402]  52.54 26.3 270 top
R109  100ohm 1% 1/16W  [R0402]  90.95 26.28 0 top
R110  47K 1% THERMISTOR NEW  [R0402]  56.95 26.01 0 top
R111  4.02K 1% 1/16W  [R0402]  49.61 25.92 180 top
R112  1K 1% 1/16W  [R0402]  109.35 25.53 0 top
R113  4.75K 1% 1/16W  [R0402]  99.61 23.65 90 top
R114  0ohm 5% 1/4W  [R1206]  43.87 22.73 180 top
R115  4.75K 1% 1/16W  [R0402]  116.53 22.56 0 top
R116  1K 1% 1/16W  [R0402]  122.27 21.87 180 top
R117  15 1% 1/10W  [R0603]  116.51 21.36 180 top
R118  10K 1% 1/16W  [R0402]  80.6 20.47 180 top
R119  *1K 1% 1/16W  [R0402]  90.35 19.62 180 top
R120  39 1% 1/10W  [R0603]  87.02 19.25 270 top
R121  1K 1% 1/16W  [R0402]  77.16 19.15 180 top
R122  4.7K 5% 1/16W  [R0402]  72.06 18.21 90 top
R123  10K 1% 1/16W  [R0402]  73.13 18.19 90 top
R124  4.75K 1% 1/16W  [R0402]  79.36 14.21 180 top
R125  4.12K 1%  [R0402]  81.26 14.21 0 top
R126  1K 1% 1/16W  [R0402]  94.61 13.34 90 top
R127  100K 1% 1/16W  [R0402]  50.24 11.58 0 top
R128  39.2K 0.1% 1/16W  [R0402]  109.61 7.54 270 top
R129  12.1K 1% 1/16W  [R0402]  145.03 4.83 90 top
R130  12.1K 1% 1/16W  [R0402]  163.32 4.45 90 top
R131  12.1K 1% 1/16W  [R0402]  145.03 2.92 90 top
R132  2.2 ohm 5% 1/16W  [R0402]  153.92 2.67 0 top
R133  12.1K 1% 1/16W  [R0402]  163.45 2.54 90 top
R134  2.2 ohm 5% 1/16W  [R0402]  172.21 2.41 0 top
R135  100ohm 1% 1/16W  [R0402]  151.38 2.29 270 top
R136  *100ohm 1% 1/16W  [R0402]  152.4 2.29 90 top
R137  100ohm 1% 1/16W  [R0402]  169.67 1.91 270 top
R138  *100ohm 1% 1/16W  [R0402]  170.69 1.91 90 top
R139  1K 1% 1/16W  [R0402]  131.7 71.17 270 bottom
R140  301  1%  1/16W  [R0402]  81.63 69.93 180 bottom
R141  4.7K 5% 1/16W  [R0402]  53.7 69.72 0 bottom
R142  3.48K 1% 1/16W  [R0402]  78.38 69.7 270 bottom
R143  301  1%  1/16W  [R0402]  81.63 68.81 180 bottom
R144  4.7K 5% 1/16W  [R0402]  53.7 68.63 0 bottom
R145  1K 1% 1/16W  [R0402]  204.98 68.07 180 bottom
R146  100K 1% 1/16W  [R0402]  123.82 67.94 270 bottom
R147  10K 1% 1/16W  [R0402]  88.04 67.84 180 bottom
R148  4.75K 1% 1/16W  [R0402]  140.21 67.82 90 bottom
R149  220 5% 1/10W  [R0603]  67.11 67.74 0 bottom
R150  301  1%  1/16W  [R0402]  28.96 66.93 180 bottom
R151  301  1%  1/16W  [R0402]  39.88 66.8 90 bottom
R152  301  1%  1/16W  [R0402]  38.86 66.8 90 bottom
R153  301  1%  1/16W  [R0402]  37.85 66.8 90 bottom
R154  301  1%  1/16W  [R0402]  35.69 66.67 90 bottom
R155  1K 1% 1/16W  [R0402]  205.1 66.55 180 bottom
R156  301  1%  1/16W  [R0402]  33.78 66.55 90 bottom
R157  7.5K  1% 1/16W  [R0402]  83.65 66.42 180 bottom
R158  301  1%  1/16W  [R0402]  28.96 65.79 180 bottom
R159  4.7K 5% 1/16W  [R0402]  63.88 65.66 0 bottom
R160  1K 1% 1/16W  [R0402]  205.1 65.53 180 bottom
R161  133 1% 1/10W  [R0603]  67.31 65.3 90 bottom
R162  10K 1% 1/16W  [R0402]  44.45 65.02 0 bottom
R163  1K 1% 1/16W  [R0402]  205.1 64.52 180 bottom
R164  51.1R 1% 1/16W  [R0402]  131.09 64.52 0 bottom
R165  1K 1% 1/16W  [R0402]  82.71 64.46 90 bottom
R166  1.87K 1% 1/10W  [R0603]  87.44 64.41 90 bottom
R167  1.87K 1% 1/10W  [R0603]  84.87 63.9 90 bottom
R168  10K 1% 1/16W  [R0402]  27.94 63.5 90 bottom
R169  10K 0.1% 1/16W  [R0402]  21.59 62.23 270 bottom
R170  10K 0.1% 1/16W  [R0402]  20.57 62.23 270 bottom
R171  10K 0.1% 1/16W  [R0402]  19.56 62.23 270 bottom
R172  4.75K 1% 1/16W  [R0402]  81.16 62.2 0 bottom
R173  1K 1% 1/16W  [R0402]  84.74 61.9 0 bottom
R174  56.2 1% 1/10W  [R0603]  87.43 61.67 180 bottom
R175  301  1%  1/16W  [R0402]  29.34 60.96 180 bottom
R176  4.7K 5% 1/16W  [R0402]  63.5 60.71 0 bottom
R177  ***10K 0.1% 1/16W  [R0402]  21.21 59.69 270 bottom
R178  ***10K 0.1% 1/16W  [R0402]  20.07 59.69 270 bottom
R179  ***10K 0.1% 1/16W  [R0402]  18.92 59.69 270 bottom
R180  *1K 1% 1/16W  [R0402]  143.49 59.42 270 bottom
R181  100K 1% 1/16W  [R0402]  145.52 59.39 270 bottom
R182  *100ohm 1% 1/16W  [R0402]  135.36 58.66 180 bottom
R183  1K 1% 1/16W  [R0402]  50.04 58.41 0 bottom
R184  240 1% 1/16W  [R0402]  103.89 58.29 90 bottom
R185  51 5% 1/16W  [R0402]  102.87 58.29 90 bottom
R186  33.2 1% 1/16W  [R0402]  44.54 58.27 180 bottom
R187  4.7K 1% 1/16W  [R0402]  19.43 57.02 0 bottom
R188  30.1 1% 1/10W  [R0603]  145.19 56.69 0 bottom
R189  100ohm 1% 1/16W  [R0402]  134.72 56.62 180 bottom
R190  10K 1% 1/16W  [R0402]  49.53 56.51 0 bottom
R191  150 5% 1/16W  [R0402]  28.47 56.11 180 bottom
R192  1K 1% 1/16W  [R0402]  18.29 55.37 180 bottom
R193  10K 0.1% 1/16W  [R0402]  22.61 54.23 180 bottom
R194  10K 0.1% 1/16W  [R0402]  20.57 54.23 180 bottom
R195  ***4.7K 1% 1/16W  [R0402]  18.29 54.23 180 bottom
R196  15ohm 1% 1/16W  [R0402]  28.7 54.1 0 bottom
R197  51 5% 1/16W  [R0402]  97.02 53.09 90 bottom
R198  51 5% 1/16W  [R0402]  112.77 52.05 90 bottom
R199  4.75K 1% 1/16W  [R0402]  26.04 51.69 90 bottom
R200  2.21K 1/16W  [R0402]  25.02 51.69 270 bottom
R201  0ohm 5% 1/16W  [R0402]  24 51.69 90 bottom
R202  *51 5% 1/16W  [R0402]  97.02 51.18 90 bottom
R203  ***4.7K 1% 1/16W  [R0402]  19.43 51.05 270 bottom
R204  ***4.7K 1% 1/16W  [R0402]  18.41 51.05 270 bottom
R205  4.7K 1% 1/16W  [R0402]  17.4 51.05 270 bottom
R206  2.21K 1/16W  [R0402]  34.85 49.96 180 bottom
R207  4.7K 1% 1/16W  [R0402]  30.22 49.76 90 bottom
R208  2.21K 1/16W  [R0402]  25.04 49.38 0 bottom
R209  0ohm 5% 1/16W  [R0402]  98.93 49.29 270 bottom
R210  10K 1% 1/16W  [R0402]  38.31 48.71 90 bottom
R211  1K 1% 1/16W  [R0402]  20.07 48.64 270 bottom
R212  1K 1% 1/16W  [R0402]  18.8 48.64 270 bottom
R213  ***52.3K 1/16W 1%  [R0402]  17.81 48.64 270 bottom
R214  0ohm 5% 1/16W  [R0402]  99.95 48.53 270 bottom
R215  0ohm 5% 1/16W  [R0402]  42.04 48.26 270 bottom
R216  10K 1% 1/16W  [R0402]  40.92 48.04 90 bottom
R217  10K 1% 1/16W  [R0402]  39.86 48.03 90 bottom
R218  4.7K 1% 1/16W  [R0402]  36.13 47.82 90 bottom
R219  402 1% 1/16W  [R0402]  127.99 46.72 270 bottom
R220  240 1% 1/16W  [R0402]  115.1 46.46 180 bottom
R221  *1K 1% 1/16W  [R0402]  120.8 44.76 180 bottom
R222  1K 1% 1/16W  [R0402]  39.85 44.6 0 bottom
R223  162 1% 0402 NEW  [R0402-HANK]  142.6 43.79 0 bottom
R224  51 5% 1/16W  [R0402]  121.89 42.79 180 bottom
R225  51 5% 1/16W  [R0402]  114.3 42.35 0 bottom
R226  1K 1% 1/16W  [R0402]  118.85 40.91 0 bottom
R227  3.01K 1% 1/16W  [R0402]  121.46 40.9 180 bottom
R228  1K 1% 1/16W  [R0402]  114.29 40.79 180 bottom
R229  15 1% 1/16W  [R0402]  36.2 40.51 0 bottom
R230  10K 1% 1/16W  [R0402]  34.16 40.13 90 bottom
R231  *1K 1% 1/16W  [R0402]  33.02 40.13 270 bottom
R232  21K 1% 1/16W  [R0402]  30.73 40.01 90 bottom
R233  10K 1% 1/16W  [R0402]  29.59 40.01 90 bottom
R234  *1K 1% 1/16W  [R0402]  28.45 40.01 270 bottom
R235  21K 1% 1/16W  [R0402]  36.2 39.5 180 bottom
R236  51 5% 1/16W  [R0402]  99.6 39.44 180 bottom
R237  *1K 1% 1/16W  [R0402]  115.14 39.43 0 bottom
R238  49.9 1% 1/16W  [R0402]  122.48 39.02 180 bottom
R239  1K 1% 1/16W  [R0402]  38.43 38.91 270 bottom
R240  10K 1% THERMISTOR NEW  [R0402]  80.9 38.89 90 bottom
R241  2.21K 1/16W  [R0402]  94.28 38.76 180 bottom
R242  100ohm 1% 1/16W  [R0402]  148.21 38.48 180 bottom
R243  10K 1% 1/16W  [R0402]  96.88 38.33 270 bottom
R244  1K 1% 1/16W  [R0402]  111.71 38.13 270 bottom
R245  *1K 1% 1/16W  [R0402]  115.42 37.59 0 bottom
R246  100ohm 1% 1/16W  [R0402]  148.21 37.47 180 bottom
R247  15 1% 1/16W  [R0402]  33.53 37.47 270 bottom
R248  15 1% 1/16W  [R0402]  32.38 37.47 270 bottom
R249  ***0ohm 5% 1/16W  [R0402]  53.09 39.78 270 bottom
R250  10K 1% 1/16W  [R0402]  96.9 36.35 270 bottom
R251  4.75K 1% 1/16W  [R0402]  58.67 35.91 180 bottom
R252  4.75K 1% 1/16W  [R0402]  53.97 35.81 270 bottom
R253  ***0ohm 5% 1/16W  [R0402]  50.16 36.83 270 bottom
R254  1M 1% 1/16W  [R0402]  113.77 35.33 180 bottom
R255  1K 1% 1/16W  [R0402]  58.67 34.81 180 bottom
R256  4.7K 1% 1/16W  [R0402]  29.46 34.8 270 bottom
R257  15 1% 1/16W  [R0402]  28.19 34.8 270 bottom
R258  15 1% 1/16W  [R0402]  26.92 34.8 270 bottom
R259  2.2 ohm 5% 1/16W  [R0402]  95.63 34.75 0 bottom
R260  4.7K 1% 1/16W  [R0402]  33.96 34.14 0 bottom
R261  49.9 1% 1/10W  [R0603]  83.16 33.93 270 bottom
R262  1K 1% 1/16W  [R0402]  56.06 33.62 270 bottom
R263  845 1% 1/16W  [R0402]  54.03 33.62 270 bottom
R264  1K 1% 1/16W  [R0402]  51.99 33.62 90 bottom
R265  845 1% 1/16W  [R0402]  50.98 33.62 270 bottom
R266  2.2 ohm 5% 1/16W  [R0402]  100.43 33.45 180 bottom
R267  10K 1% 1/16W  [R0402]  109.35 32.9 180 bottom
R268  44.2K 1% 1/16W  [R0402]  20.83 32.77 180 bottom
R269  10K 1% 1/16W  [R0402]  106.17 31.88 270 bottom
R270  10K 1% 1/16W  [R0402]  109.35 31.85 0 bottom
R271  10K 1% 1/16W  [R0402]  116.99 31.64 0 bottom
R272  402 1% 1/16W  [R0402]  119.02 31.57 0 bottom
R273  4.75K 1% 1/16W  [R0402]  58.42 31.5 180 bottom
R274  162 1% 0402 NEW  [R0402-HANK]  130.2 31.24 270 bottom
R275  100K 1% 1/16W  [R0402]  142.21 31.06 90 bottom
R276  1 5% 1/16W  [R0402]  63.25 30.86 0 bottom
R277  1K 1% 1/16W  [R0402]  109.36 30.82 180 bottom
R278  10K 1% 1/16W  [R0402]  118.06 30.61 0 bottom
R279  7.5K  1% 1/16W  [R0402]  56.34 30.61 0 bottom
R280  100ohm 1% 1/16W  [R0402]  47.12 30.1 270 bottom
R281  33 1% 1/16W  [R0402]  104.52 29.97 270 bottom
R282  10K 1% 1/16W  [R0402]  109.35 29.75 180 bottom
R283  402 1% 1/16W  [R0402]  120.24 29.45 270 bottom
R284  301  1%  1/16W  [R0402]  57.66 29.43 0 bottom
R285  402 1% 1/16W  [R0402]  122.1 29.36 270 bottom
R286  100ohm 1% 1/16W  [R0402]  204.98 29.34 0 bottom
R287  3.4K 1% 1/16W  [R0402]  60.58 29.05 270 bottom
R288  10K 1% 1/16W  [R0402]  109.37 28.71 0 bottom
R289  1K 1% 1/16W  [R0402]  107.37 28.5 90 bottom
R290  301  1%  1/16W  [R0402]  57.66 28.41 0 bottom
R291  100ohm 1% 1/16W  [R0402]  204.98 28.32 180 bottom
R292  *1K 1% 1/16W  [R0402]  143 28.28 90 bottom
R293  *2.21K 1/16W  [R0402]  95.18 28.22 0 bottom
R294  10K 1% 1/16W  [R0402]  117.78 28.15 0 bottom
R295  10K 1% 1/16W  [R0402]  119.84 27.95 180 bottom
R296  ***100ohm 1% 1/16W  [R0402]  52.45 27.81 180 bottom
R297  10K 1% 1/16W  [R0402]  109.39 27.65 0 bottom
R298  100ohm 1% 1/16W  [R0402]  146.03 27.41 270 bottom
R299  100ohm 1% 1/16W  [R0402]  204.98 27.3 0 bottom
R300  15ohm 1% 1/16W  [R0402]  112.02 27.23 270 bottom
R301  10K 1% 1/16W  [R0402]  109.38 26.59 0 bottom
R302  0ohm 5% 1/4W  [R1206]  72.29 26.49 0 bottom
R303  *1K 1% 1/16W  [R0402]  118.91 26.49 0 bottom
R304  1K 1% 1/16W  [R0402]  120.8 26.16 0 bottom
R305  *10K 1% 1/16W  [R0402]  106.15 26.02 270 bottom
R306  30.1 1% 1/10W  [R0603]  132.11 25.78 180 bottom
R307  15ohm 1% 1/16W  [R0402]  104.6 25.55 0 bottom
R308  15ohm 1% 1/16W  [R0402]  109.35 25.54 180 bottom
R309  100ohm 1% 1/16W  [R0402]  204.98 25.27 180 bottom
R310  15ohm 1% 1/16W  [R0402]  109.35 24.47 180 bottom
R311  100ohm 1% 1/16W  [R0402]  143.23 24.37 0 bottom
R312  10K 1% 1/16W  [R0402]  105.99 24 180 bottom
R313  4.75K 1% 1/16W  [R0402]  119.31 23.7 270 bottom
